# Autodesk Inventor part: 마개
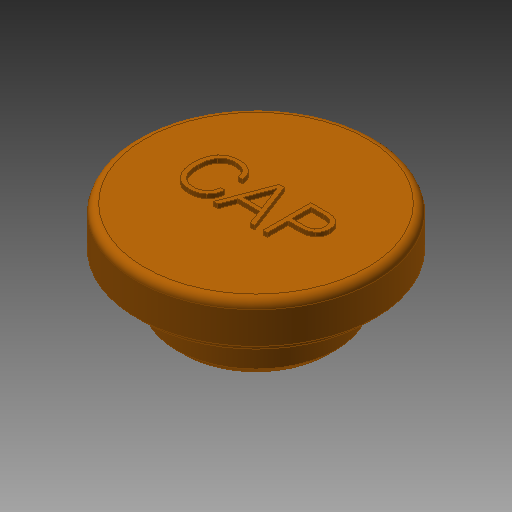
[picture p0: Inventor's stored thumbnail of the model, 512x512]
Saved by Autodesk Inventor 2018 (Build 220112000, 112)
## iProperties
Created: 2018-03
Part Number: 마개
Material: 고무
Document SubType Name: Modeling
Designer: mduedu
Density: 1 g/cm^3
Appearance: 주황색
Author: mduedu
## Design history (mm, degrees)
sketch "스케치1"
  geometry: C1 r 15 at (0, 0); 1 further point
  constraints: 1 centre point, 1 coincident
  dimensions: "d21" = 30 diameter of C1
extrude "돌출1" new body sketch "스케치1" distance "d2" = 6; taper "d3" = 0 deg
fillet "모깎기4" dims "d22" = 1
sketch "스케치6"
  geometry: C1 r 10 at (0, 0); 1 further point
  constraints: 1 centre point, 1 coincident
  dimensions: "d23" = 20 diameter of C1
extrude "돌출5" join sketch "스케치6" distance "d24" = 6; taper "d25" = 0 deg
sketch "스케치7"
  geometry: C1 r 7.5 at (0, 0); 1 further point
  constraints: 1 centre point, 1 coincident
  dimensions: "d26" = 15 diameter of C1
extrude "돌출6" cut sketch "스케치7" distance "d27" = 6; taper "d28" = 0 deg
sketch "스케치8"
  geometry: C1 r 15 at (0, 0) reference; C2 r 14 at (0, 0); 1 further point
  constraints: 1 centre point, 1 coincident
  dimensions: "d29" = 1 radial gap between concentric circles of C2 C1
extrude "돌출7" cut sketch "스케치8" distance "d30" = 1; taper "d31" = 0 deg
fillet "모깎기5" dims "d32" = 1
chamfer "모따기2" distance "d33" = 1; stored, may be unused: second distance "d34" = 2, angle "d35" = 45 deg
sketch "스케치5"
  geometry: 2 further points
  constraints: 1 coincident, 1 other
feature "엠보싱1" sketch "스케치5" dims "d19" = 0.5, "d20" = 0
node "솔리드1"
